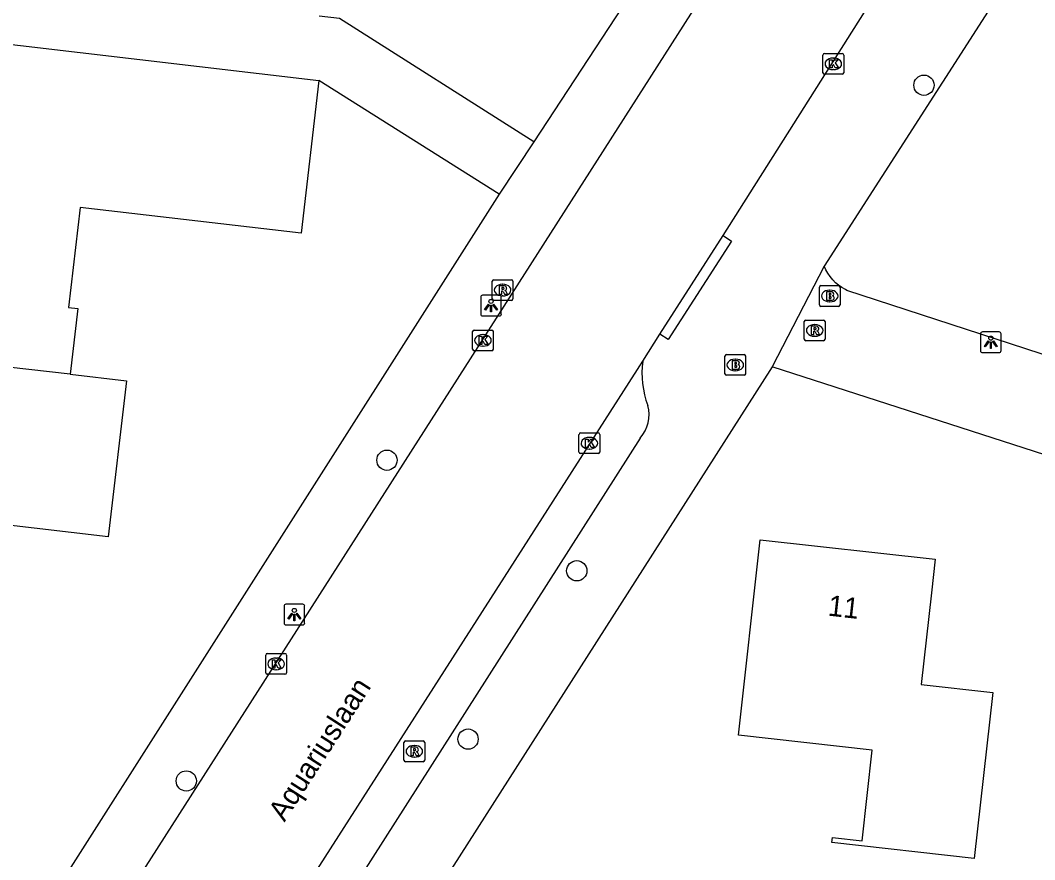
# Model space of a CAD drawing. Extents: x 162398 to 163643, y 386453 to 387397.
# Drawn here: x 162779.38 to 162828.35, y 386780.36 to 386820.85 of the extents above; entities that cross this region are included whole.
import ezdxf

# ---------------------------------------------------------------- set-up
doc = ezdxf.new("R2010")
doc.units = 0
for name, color, linetype in [('IMGEO_Boom', 7, 'Continuous'), ('IMGEO_Brandkraan', 7, 'Continuous'), ('IMGEO_Kolk', 7, 'Continuous'), ('IMGEO_Lichtpunt', 7, 'Continuous'), ('IMGEO_Openbare_ruimte_label', 7, 'Continuous'), ('IMGEO_Pand', 7, 'Continuous'), ('IMGEO_Pand_nummerreeks', 7, 'Continuous'), ('IMGEO_Rijbaan_lokaal_open', 7, 'Continuous'), ('IMGEO_Rioolput', 7, 'Continuous'), ('IMGEO_Voetpad_open', 7, 'Continuous')]:
    doc.layers.add(name, color=color, linetype=linetype)

msp = doc.modelspace()

# ---------------------------------------------------------------- linework, layer by layer
at = {"layer": 'IMGEO_Boom'}
for centre in [(162823.005, 386817.72), (162797.085, 386799.631), (162806.246, 386794.298), (162800.998, 386786.178), (162787.398, 386784.157)]:
    msp.add_circle(centre, 0.489, dxfattribs=at)
at = {"layer": 'IMGEO_Brandkraan'}
for p, q in [((162817.954, 386807.127), (162817.954, 386807.979)), ((162818.029, 386808.053), (162818.881, 386808.053)), ((162818.442, 386807.833), (162818.467, 386807.833)), ((162818.955, 386807.979), (162818.955, 386807.127)), ((162818.465, 386807.273), (162818.44, 386807.273)), ((162818.881, 386807.053), (162818.029, 386807.053)), ((162813.397, 386803.8), (162813.397, 386804.652)), ((162813.472, 386804.726), (162814.324, 386804.726)), ((162813.885, 386804.506), (162813.91, 386804.506)), ((162814.398, 386804.652), (162814.398, 386803.8)), ((162813.908, 386803.946), (162813.883, 386803.946)), ((162814.324, 386803.726), (162813.472, 386803.726))]:
    msp.add_line(p, q, dxfattribs=at)
for points in [[(162817.954, 386807.127), (162817.954, 386807.979)], [(162818.029, 386808.053), (162818.881, 386808.053)], [(162818.302, 386807.753), (162818.302, 386807.353), (162818.515, 386807.353)], [(162818.533, 386807.753), (162818.302, 386807.753)], [(162818.955, 386807.979), (162818.955, 386807.127)], [(162818.481, 386807.672), (162818.427, 386807.672), (162818.427, 386807.596)], [(162818.427, 386807.596), (162818.48, 386807.596)], [(162818.489, 386807.52), (162818.427, 386807.52), (162818.427, 386807.439)], [(162818.427, 386807.439), (162818.489, 386807.439)], [(162818.881, 386807.053), (162818.029, 386807.053)], [(162813.397, 386803.8), (162813.397, 386804.652)], [(162813.472, 386804.726), (162814.324, 386804.726)], [(162813.745, 386804.426), (162813.745, 386804.026), (162813.958, 386804.026)], [(162813.976, 386804.426), (162813.745, 386804.426)], [(162813.924, 386804.345), (162813.87, 386804.345), (162813.87, 386804.269)], [(162813.87, 386804.269), (162813.923, 386804.269)], [(162814.398, 386804.652), (162814.398, 386803.8)], [(162813.932, 386804.193), (162813.87, 386804.193), (162813.87, 386804.112)], [(162813.87, 386804.112), (162813.932, 386804.112)], [(162814.324, 386803.726), (162813.472, 386803.726)]]:
    msp.add_lwpolyline(points, dxfattribs=at)
for centre, radius, start, end in [((162818.031, 386807.977), 0.0765, 91.552, 178.448), ((162818.031, 386807.977), 0.0765, 91.552, 178.448), ((162818.537, 386807.608), 0.145, 59.4692, 91.5367), ((162818.562, 386807.655), 0.0922, 285.5137, 58.1501), ((162818.879, 386807.977), 0.0765, 1.552, 88.448), ((162818.879, 386807.977), 0.0765, 1.552, 88.448), ((162818.482, 386807.634), 0.0379, 267.8285, 90.9355), ((162818.49, 386807.479), 0.0404, 269.8759, 90.5077), ((162818.521, 386807.604), 0.251, 268.6676, 293.5347), ((162818.567, 386807.463), 0.105, 301.3115, 78.989), ((162818.031, 386807.129), 0.0765, 181.552, 268.448), ((162818.031, 386807.129), 0.0765, 181.552, 268.448), ((162818.879, 386807.129), 0.0765, 271.552, 358.448), ((162818.879, 386807.129), 0.0765, 271.552, 358.448), ((162813.474, 386804.65), 0.0765, 91.552, 178.448), ((162813.474, 386804.65), 0.0765, 91.552, 178.448), ((162813.925, 386804.307), 0.0379, 267.8285, 90.9355), ((162813.98, 386804.281), 0.145, 59.4692, 91.5367), ((162814.005, 386804.328), 0.0922, 285.5137, 58.1501), ((162814.322, 386804.65), 0.0765, 1.552, 88.448), ((162814.322, 386804.65), 0.0765, 1.552, 88.448), ((162813.474, 386803.802), 0.0765, 181.552, 268.448), ((162813.474, 386803.802), 0.0765, 181.552, 268.448), ((162813.933, 386804.152), 0.0404, 269.8759, 90.5077), ((162813.964, 386804.277), 0.251, 268.6676, 293.5347), ((162814.01, 386804.136), 0.105, 301.3115, 78.989), ((162814.322, 386803.802), 0.0765, 271.552, 358.448), ((162814.322, 386803.802), 0.0765, 271.552, 358.448)]:
    msp.add_arc(centre, radius, start, end, dxfattribs=at)
for centre, major_axis, ratio, start_param, end_param in [((162818.441, 386807.553), (-0.387, 0.002), 0.722429, 4.712389, 7.853982), ((162818.466, 386807.553), (-0.39, 0.002), 0.717154, 1.570796, 4.712389), ((162813.884, 386804.226), (-0.387, 0.002), 0.722429, 4.712389, 7.853982), ((162813.909, 386804.226), (-0.39, 0.002), 0.717154, 1.570796, 4.712389)]:
    msp.add_ellipse(centre, major_axis=major_axis, ratio=ratio, start_param=start_param, end_param=end_param, dxfattribs=at)
at = {"layer": 'IMGEO_Kolk'}
for p, q in [((162818.128, 386818.325), (162818.128, 386819.177)), ((162818.203, 386819.251), (162819.055, 386819.251)), ((162818.616, 386819.031), (162818.641, 386819.031)), ((162819.129, 386819.177), (162819.129, 386818.325)), ((162818.639, 386818.471), (162818.614, 386818.471)), ((162819.055, 386818.251), (162818.203, 386818.251)), ((162801.217, 386804.985), (162801.217, 386805.837)), ((162801.292, 386805.911), (162802.144, 386805.911)), ((162802.218, 386805.837), (162802.218, 386804.985)), ((162801.705, 386805.691), (162801.73, 386805.691)), ((162802.144, 386804.911), (162801.292, 386804.911)), ((162801.728, 386805.131), (162801.703, 386805.131)), ((162806.353, 386800.024), (162806.353, 386800.876)), ((162806.428, 386800.95), (162807.28, 386800.95)), ((162807.354, 386800.876), (162807.354, 386800.024)), ((162806.841, 386800.73), (162806.866, 386800.73)), ((162807.28, 386799.95), (162806.428, 386799.95)), ((162806.864, 386800.17), (162806.839, 386800.17)), ((162791.233, 386789.379), (162791.233, 386790.231)), ((162791.308, 386790.305), (162792.16, 386790.305)), ((162791.721, 386790.085), (162791.746, 386790.085)), ((162792.234, 386790.231), (162792.234, 386789.379)), ((162792.16, 386789.305), (162791.308, 386789.305)), ((162791.744, 386789.525), (162791.719, 386789.525))]:
    msp.add_line(p, q, dxfattribs=at)
for points in [[(162818.128, 386818.325), (162818.128, 386819.177)], [(162818.203, 386819.251), (162819.055, 386819.251)], [(162818.449, 386818.951), (162818.572, 386818.951), (162818.572, 386818.8), (162818.702, 386818.951), (162818.866, 386818.951), (162818.72, 386818.8), (162818.873, 386818.551), (162818.721, 386818.551), (162818.636, 386818.715), (162818.572, 386818.648), (162818.572, 386818.551), (162818.449, 386818.551), (162818.449, 386818.951)], [(162819.129, 386819.177), (162819.129, 386818.325)], [(162819.055, 386818.251), (162818.203, 386818.251)], [(162801.217, 386804.985), (162801.217, 386805.837)], [(162801.292, 386805.911), (162802.144, 386805.911)], [(162802.218, 386805.837), (162802.218, 386804.985)], [(162801.538, 386805.611), (162801.661, 386805.611), (162801.661, 386805.46), (162801.791, 386805.611), (162801.955, 386805.611), (162801.809, 386805.46), (162801.962, 386805.211), (162801.81, 386805.211), (162801.725, 386805.375), (162801.661, 386805.308), (162801.661, 386805.211), (162801.538, 386805.211), (162801.538, 386805.611)], [(162802.144, 386804.911), (162801.292, 386804.911)], [(162806.353, 386800.024), (162806.353, 386800.876)], [(162806.428, 386800.95), (162807.28, 386800.95)], [(162807.354, 386800.876), (162807.354, 386800.024)], [(162806.674, 386800.65), (162806.797, 386800.65), (162806.797, 386800.499), (162806.927, 386800.65), (162807.091, 386800.65), (162806.945, 386800.499), (162807.098, 386800.25), (162806.946, 386800.25), (162806.861, 386800.414), (162806.797, 386800.347), (162806.797, 386800.25), (162806.674, 386800.25), (162806.674, 386800.65)], [(162807.28, 386799.95), (162806.428, 386799.95)], [(162791.233, 386789.379), (162791.233, 386790.231)], [(162791.308, 386790.305), (162792.16, 386790.305)], [(162792.234, 386790.231), (162792.234, 386789.379)], [(162791.554, 386790.005), (162791.677, 386790.005), (162791.677, 386789.854), (162791.807, 386790.005), (162791.971, 386790.005), (162791.825, 386789.854), (162791.978, 386789.605), (162791.826, 386789.605), (162791.741, 386789.769), (162791.677, 386789.702), (162791.677, 386789.605), (162791.554, 386789.605), (162791.554, 386790.005)], [(162792.16, 386789.305), (162791.308, 386789.305)]]:
    msp.add_lwpolyline(points, dxfattribs=at)
for centre, start, end in [((162818.205, 386819.175), 91.552, 178.448), ((162818.205, 386819.175), 91.552, 178.448), ((162819.053, 386819.175), 1.552, 88.448), ((162819.053, 386819.175), 1.552, 88.448), ((162818.205, 386818.327), 181.552, 268.448), ((162818.205, 386818.327), 181.552, 268.448), ((162819.053, 386818.327), 271.552, 358.448), ((162819.053, 386818.327), 271.552, 358.448), ((162801.294, 386805.835), 91.552, 178.448), ((162801.294, 386805.835), 91.552, 178.448), ((162802.142, 386805.835), 1.552, 88.448), ((162802.142, 386805.835), 1.552, 88.448), ((162801.294, 386804.987), 181.552, 268.448), ((162801.294, 386804.987), 181.552, 268.448), ((162802.142, 386804.987), 271.552, 358.448), ((162802.142, 386804.987), 271.552, 358.448), ((162806.43, 386800.874), 91.552, 178.448), ((162806.43, 386800.874), 91.552, 178.448), ((162807.278, 386800.874), 1.552, 88.448), ((162807.278, 386800.874), 1.552, 88.448), ((162806.43, 386800.026), 181.552, 268.448), ((162806.43, 386800.026), 181.552, 268.448), ((162807.278, 386800.026), 271.552, 358.448), ((162807.278, 386800.026), 271.552, 358.448), ((162791.31, 386790.229), 91.552, 178.448), ((162791.31, 386790.229), 91.552, 178.448), ((162792.158, 386790.229), 1.552, 88.448), ((162792.158, 386790.229), 1.552, 88.448), ((162791.31, 386789.381), 181.552, 268.448), ((162791.31, 386789.381), 181.552, 268.448), ((162792.158, 386789.381), 271.552, 358.448), ((162792.158, 386789.381), 271.552, 358.448)]:
    msp.add_arc(centre, 0.0765, start, end, dxfattribs=at)
for centre, major_axis, ratio, start_param, end_param in [((162818.615, 386818.751), (-0.387, 0.002), 0.722429, 4.712389, 7.853982), ((162818.64, 386818.751), (-0.39, 0.002), 0.717154, 1.570796, 4.712389), ((162801.704, 386805.411), (-0.387, 0.002), 0.722429, 4.712389, 7.853982), ((162801.729, 386805.411), (-0.39, 0.002), 0.717154, 1.570796, 4.712389), ((162806.84, 386800.45), (-0.387, 0.002), 0.722429, 4.712389, 7.853982), ((162806.865, 386800.45), (-0.39, 0.002), 0.717154, 1.570796, 4.712389), ((162791.72, 386789.805), (-0.387, 0.002), 0.722429, 4.712389, 7.853982), ((162791.745, 386789.805), (-0.39, 0.002), 0.717154, 1.570796, 4.712389)]:
    msp.add_ellipse(centre, major_axis=major_axis, ratio=ratio, start_param=start_param, end_param=end_param, dxfattribs=at)
at = {"layer": 'IMGEO_Lichtpunt'}
for p, q in [((162801.608, 386807.493), (162801.608, 386806.686)), ((162801.608, 386807.493), (162801.608, 386806.686)), ((162802.51, 386807.588), (162801.702, 386807.588)), ((162802.51, 386807.588), (162801.702, 386807.588)), ((162802.604, 386806.686), (162802.604, 386807.493)), ((162802.604, 386806.686), (162802.604, 386807.493)), ((162801.702, 386806.592), (162802.51, 386806.592)), ((162801.702, 386806.592), (162802.51, 386806.592)), ((162826.635, 386805.818), (162825.827, 386805.818)), ((162826.635, 386805.818), (162825.827, 386805.818)), ((162825.733, 386805.723), (162825.733, 386804.916)), ((162825.733, 386805.723), (162825.733, 386804.916)), ((162826.729, 386804.916), (162826.729, 386805.723)), ((162826.729, 386804.916), (162826.729, 386805.723)), ((162825.827, 386804.822), (162826.635, 386804.822)), ((162825.827, 386804.822), (162826.635, 386804.822)), ((162792.115, 386792.588), (162792.115, 386791.781)), ((162792.115, 386792.588), (162792.115, 386791.781)), ((162793.017, 386792.683), (162792.209, 386792.683)), ((162793.017, 386792.683), (162792.209, 386792.683)), ((162793.111, 386791.781), (162793.111, 386792.588)), ((162793.111, 386791.781), (162793.111, 386792.588)), ((162792.209, 386791.687), (162793.017, 386791.687)), ((162792.209, 386791.687), (162793.017, 386791.687))]:
    msp.add_line(p, q, dxfattribs=at)
for points in [[(162801.982, 386807.157), (162802.021, 386807.129), (162801.833, 386806.867), (162801.795, 386806.894), (162801.982, 386807.157)], [(162802.084, 386807.109), (162802.131, 386807.109), (162802.131, 386806.787), (162802.084, 386806.787), (162802.084, 386807.109)], [(162802.194, 386807.129), (162802.232, 386807.156), (162802.419, 386806.894), (162802.38, 386806.866), (162802.194, 386807.129)], [(162826.107, 386805.387), (162826.146, 386805.359), (162825.958, 386805.097), (162825.92, 386805.124), (162826.107, 386805.387)], [(162826.209, 386805.339), (162826.256, 386805.339), (162826.256, 386805.017), (162826.209, 386805.017), (162826.209, 386805.339)], [(162826.319, 386805.359), (162826.357, 386805.386), (162826.544, 386805.124), (162826.505, 386805.096), (162826.319, 386805.359)], [(162792.489, 386792.252), (162792.528, 386792.224), (162792.34, 386791.962), (162792.302, 386791.989), (162792.489, 386792.252)], [(162792.591, 386792.204), (162792.638, 386792.204), (162792.638, 386791.882), (162792.591, 386791.882), (162792.591, 386792.204)], [(162792.701, 386792.224), (162792.739, 386792.251), (162792.926, 386791.989), (162792.887, 386791.961), (162792.701, 386792.224)]]:
    msp.add_lwpolyline(points, dxfattribs=at)
for centre in [(162802.107, 386807.291), (162826.232, 386805.521), (162792.614, 386792.386)]:
    msp.add_circle(centre, 0.0994, dxfattribs=at)
for centre, start, end in [((162801.702, 386807.493), 90, 180), ((162801.702, 386807.493), 90, 180), ((162802.51, 386807.493), 0, 90), ((162802.51, 386807.493), 0, 90), ((162801.702, 386806.686), 180, 270), ((162801.702, 386806.686), 180, 270), ((162802.51, 386806.686), 270, 0), ((162802.51, 386806.686), 270, 360), ((162825.827, 386805.723), 90, 180), ((162825.827, 386805.723), 90, 180), ((162826.635, 386805.723), 0, 90), ((162826.635, 386805.723), 0, 90), ((162825.827, 386804.916), 180, 270), ((162825.827, 386804.916), 180, 270), ((162826.635, 386804.916), 270, 0), ((162826.635, 386804.916), 270, 360), ((162792.209, 386792.588), 90, 180), ((162792.209, 386792.588), 90, 180), ((162793.017, 386792.588), 0, 90), ((162793.017, 386792.588), 0, 90), ((162792.209, 386791.781), 180, 270), ((162792.209, 386791.781), 180, 270), ((162793.017, 386791.781), 270, 0), ((162793.017, 386791.781), 270, 360)]:
    msp.add_arc(centre, 0.0946, start, end, dxfattribs=at)
at = {"layer": 'IMGEO_Pand'}
for points in [[(162776.506, 386819.973), (162793.802, 386817.953)], [(162793.802, 386817.953), (162792.941, 386810.576), (162782.274, 386811.821), (162781.711, 386806.996), (162782.162, 386806.943), (162781.792, 386803.775)], [(162781.792, 386803.775), (162774.936, 386804.548)], [(162781.792, 386803.775), (162784.511, 386803.458), (162783.632, 386795.93), (162772.894, 386797.183), (162772.33, 386792.35), (162772.735, 386792.303), (162772.367, 386789.15)], [(162818.565, 386781.189), (162818.593, 386781.433), (162820.025, 386781.274), (162820.511, 386785.65), (162814.045, 386786.369), (162815.093, 386795.798), (162823.543, 386794.858), (162823.363, 386793.237), (162822.871, 386788.813), (162826.321, 386788.429), (162825.432, 386780.425), (162818.565, 386781.189)]]:
    msp.add_lwpolyline(points, dxfattribs=at)
at = {"layer": 'IMGEO_Rijbaan_lokaal_open'}
for points in [[(162768.682, 386753.831), (162820.766, 386835.256), (162822.004, 386837.173), (162822.433, 386837.832)], [(162813.306, 386810.463), (162826.152, 386830.756), (162828.282, 386834.044)], [(162810.261, 386805.711), (162813.306, 386810.463)], [(162818.187, 386808.997), (162815.673, 386804.14)], [(162845.898, 386799.152), (162819.285, 386807.824), (162819.217, 386807.858), (162819.047, 386807.956), (162818.887, 386808.068), (162818.737, 386808.195), (162818.599, 386808.334), (162818.474, 386808.485), (162818.363, 386808.647), (162818.267, 386808.818), (162818.187, 386808.997)], [(162809.431, 386804.415), (162810.261, 386805.711)], [(162780.603, 386759.42), (162809.431, 386804.415)], [(162912.129, 386756.249), (162869.085, 386783.465), (162860.954, 386788.148), (162853.712, 386791.497), (162844.55, 386794.823), (162815.673, 386804.14)]]:
    msp.add_lwpolyline(points, dxfattribs=at)
at = {"layer": 'IMGEO_Rioolput'}
for p, q in [((162802.166, 386807.412), (162802.166, 386808.264)), ((162802.241, 386808.338), (162803.093, 386808.338)), ((162803.167, 386808.264), (162803.167, 386807.412)), ((162802.654, 386808.118), (162802.679, 386808.118)), ((162803.093, 386807.338), (162802.241, 386807.338)), ((162802.677, 386807.558), (162802.652, 386807.558)), ((162817.229, 386805.466), (162817.229, 386806.318)), ((162817.304, 386806.392), (162818.156, 386806.392)), ((162818.23, 386806.318), (162818.23, 386805.466)), ((162817.717, 386806.172), (162817.742, 386806.172)), ((162818.156, 386805.392), (162817.304, 386805.392)), ((162817.74, 386805.612), (162817.715, 386805.612)), ((162797.904, 386785.162), (162797.904, 386786.014)), ((162797.979, 386786.088), (162798.831, 386786.088)), ((162798.392, 386785.868), (162798.417, 386785.868)), ((162798.905, 386786.014), (162798.905, 386785.162)), ((162798.415, 386785.308), (162798.39, 386785.308)), ((162798.831, 386785.088), (162797.979, 386785.088))]:
    msp.add_line(p, q, dxfattribs=at)
for points in [[(162802.166, 386807.412), (162802.166, 386808.264)], [(162802.241, 386808.338), (162803.093, 386808.338)], [(162803.167, 386808.264), (162803.167, 386807.412)], [(162802.755, 386808.036), (162802.503, 386808.038), (162802.503, 386807.638)], [(162802.503, 386807.638), (162802.627, 386807.638), (162802.627, 386807.8), (162802.638, 386807.8)], [(162802.681, 386807.957), (162802.627, 386807.957), (162802.627, 386807.876)], [(162802.627, 386807.876), (162802.679, 386807.876)], [(162802.685, 386807.771), (162802.756, 386807.638), (162802.896, 386807.638), (162802.831, 386807.764)], [(162803.093, 386807.338), (162802.241, 386807.338)], [(162817.229, 386805.466), (162817.229, 386806.318)], [(162817.304, 386806.392), (162818.156, 386806.392)], [(162818.23, 386806.318), (162818.23, 386805.466)], [(162817.818, 386806.09), (162817.566, 386806.092), (162817.566, 386805.692)], [(162817.566, 386805.692), (162817.69, 386805.692), (162817.69, 386805.854), (162817.701, 386805.854)], [(162817.744, 386806.011), (162817.69, 386806.011), (162817.69, 386805.93)], [(162817.69, 386805.93), (162817.742, 386805.93)], [(162817.748, 386805.825), (162817.819, 386805.692), (162817.959, 386805.692), (162817.894, 386805.818)], [(162818.156, 386805.392), (162817.304, 386805.392)], [(162797.904, 386785.162), (162797.904, 386786.014)], [(162797.979, 386786.088), (162798.831, 386786.088)], [(162798.493, 386785.786), (162798.241, 386785.788), (162798.241, 386785.388)], [(162798.419, 386785.707), (162798.365, 386785.707), (162798.365, 386785.626)], [(162798.905, 386786.014), (162798.905, 386785.162)], [(162798.241, 386785.388), (162798.365, 386785.388), (162798.365, 386785.55), (162798.376, 386785.55)], [(162798.365, 386785.626), (162798.417, 386785.626)], [(162798.423, 386785.521), (162798.494, 386785.388), (162798.634, 386785.388), (162798.569, 386785.514)], [(162798.831, 386785.088), (162797.979, 386785.088)]]:
    msp.add_lwpolyline(points, dxfattribs=at)
for centre, radius, start, end in [((162802.243, 386808.262), 0.0765, 91.552, 178.448), ((162802.243, 386808.262), 0.0765, 91.552, 178.448), ((162803.091, 386808.262), 0.0765, 1.552, 88.448), ((162803.091, 386808.262), 0.0765, 1.552, 88.448), ((162802.637, 386807.747), 0.0533, 26.0293, 88.6989), ((162802.663, 386808.065), 0.19, 274.7715, 282.9687), ((162802.687, 386807.861), 0.0964, 77.0061, 93.1865), ((162802.701, 386807.918), 0.0378, 276.6634, 79.6772), ((162802.754, 386807.926), 0.109, 350.3612, 89.416), ((162802.752, 386807.926), 0.112, 277.5842, 350.9817), ((162802.736, 386807.711), 0.108, 29.5134, 73.7905), ((162802.243, 386807.414), 0.0765, 181.552, 268.448), ((162802.243, 386807.414), 0.0765, 181.552, 268.448), ((162803.091, 386807.414), 0.0765, 271.552, 358.448), ((162803.091, 386807.414), 0.0765, 271.552, 358.448), ((162817.306, 386806.316), 0.0765, 91.552, 178.448), ((162817.306, 386806.316), 0.0765, 91.552, 178.448), ((162818.154, 386806.316), 0.0765, 1.552, 88.448), ((162818.154, 386806.316), 0.0765, 1.552, 88.448), ((162817.7, 386805.801), 0.0533, 26.0293, 88.6989), ((162817.726, 386806.119), 0.19, 274.7715, 282.9687), ((162817.75, 386805.915), 0.0964, 77.0061, 93.1865), ((162817.764, 386805.972), 0.0378, 276.6634, 79.6772), ((162817.817, 386805.98), 0.109, 350.3612, 89.416), ((162817.815, 386805.98), 0.112, 277.5842, 350.9817), ((162817.799, 386805.765), 0.108, 29.5134, 73.7905), ((162817.306, 386805.468), 0.0765, 181.552, 268.448), ((162817.306, 386805.468), 0.0765, 181.552, 268.448), ((162818.154, 386805.468), 0.0765, 271.552, 358.448), ((162818.154, 386805.468), 0.0765, 271.552, 358.448), ((162797.981, 386786.012), 0.0765, 91.552, 178.448), ((162797.981, 386786.012), 0.0765, 91.552, 178.448), ((162798.425, 386785.611), 0.0964, 77.0061, 93.1865), ((162798.439, 386785.668), 0.0378, 276.6634, 79.6772), ((162798.492, 386785.676), 0.109, 350.3612, 89.416), ((162798.49, 386785.676), 0.112, 277.5842, 350.9817), ((162798.829, 386786.012), 0.0765, 1.552, 88.448), ((162798.829, 386786.012), 0.0765, 1.552, 88.448), ((162798.375, 386785.497), 0.0533, 26.0293, 88.6989), ((162798.401, 386785.815), 0.19, 274.7715, 282.9687), ((162798.474, 386785.461), 0.108, 29.5134, 73.7905), ((162797.981, 386785.164), 0.0765, 181.552, 268.448), ((162797.981, 386785.164), 0.0765, 181.552, 268.448), ((162798.829, 386785.164), 0.0765, 271.552, 358.448), ((162798.829, 386785.164), 0.0765, 271.552, 358.448)]:
    msp.add_arc(centre, radius, start, end, dxfattribs=at)
for centre, major_axis, ratio, start_param, end_param in [((162802.653, 386807.838), (-0.387, 0.002), 0.722429, 4.712389, 7.853982), ((162802.678, 386807.838), (-0.39, 0.002), 0.717154, 1.570796, 4.712389), ((162817.716, 386805.892), (-0.387, 0.002), 0.722429, 4.712389, 7.853982), ((162817.741, 386805.892), (-0.39, 0.002), 0.717154, 1.570796, 4.712389), ((162798.391, 386785.588), (-0.387, 0.002), 0.722429, 4.712389, 7.853982), ((162798.416, 386785.588), (-0.39, 0.002), 0.717154, 1.570796, 4.712389)]:
    msp.add_ellipse(centre, major_axis=major_axis, ratio=ratio, start_param=start_param, end_param=end_param, dxfattribs=at)
at = {"layer": 'IMGEO_Voetpad_open'}
for points in [[(162835.669, 386836.289), (162832.891, 386832.055), (162832.389, 386831.084), (162818.187, 386808.997)], [(162809.763, 386823.512), (162804.178, 386814.988)], [(162804.178, 386814.988), (162794.788, 386820.942), (162793.816, 386821.057)], [(162802.507, 386812.457), (162793.802, 386817.953)], [(162804.178, 386814.988), (162802.507, 386812.457)], [(162802.507, 386812.457), (162766.009, 386755.197)], [(162813.306, 386810.463), (162813.708, 386810.205), (162810.659, 386805.455), (162810.261, 386805.711)], [(162815.673, 386804.14), (162784.464, 386755.3)], [(162809.308, 386800.697), (162783.978, 386761.029)]]:
    msp.add_lwpolyline(points, dxfattribs=at)
for centre, radius, start, end in [((162813.973, 386803.836), 4.579, 172.7375, 200.0949), ((162808.07, 386801.811), 1.665, 318.0157, 15.744)]:
    msp.add_arc(centre, radius, start, end, dxfattribs=at)

# ---------------------------------------------------------------- texts
at = {"layer": 'IMGEO_Openbare_ruimte_label'}
msp.add_text('Aquariuslaan', height=1, rotation=57.2958, dxfattribs=at).set_placement((162792.137, 386782.148))
at = {"layer": 'IMGEO_Pand_nummerreeks'}
msp.add_text('11', height=1, rotation=353.6524, dxfattribs=at).set_placement((162818.338, 386792.138))

doc.saveas('drawing.dxf')
